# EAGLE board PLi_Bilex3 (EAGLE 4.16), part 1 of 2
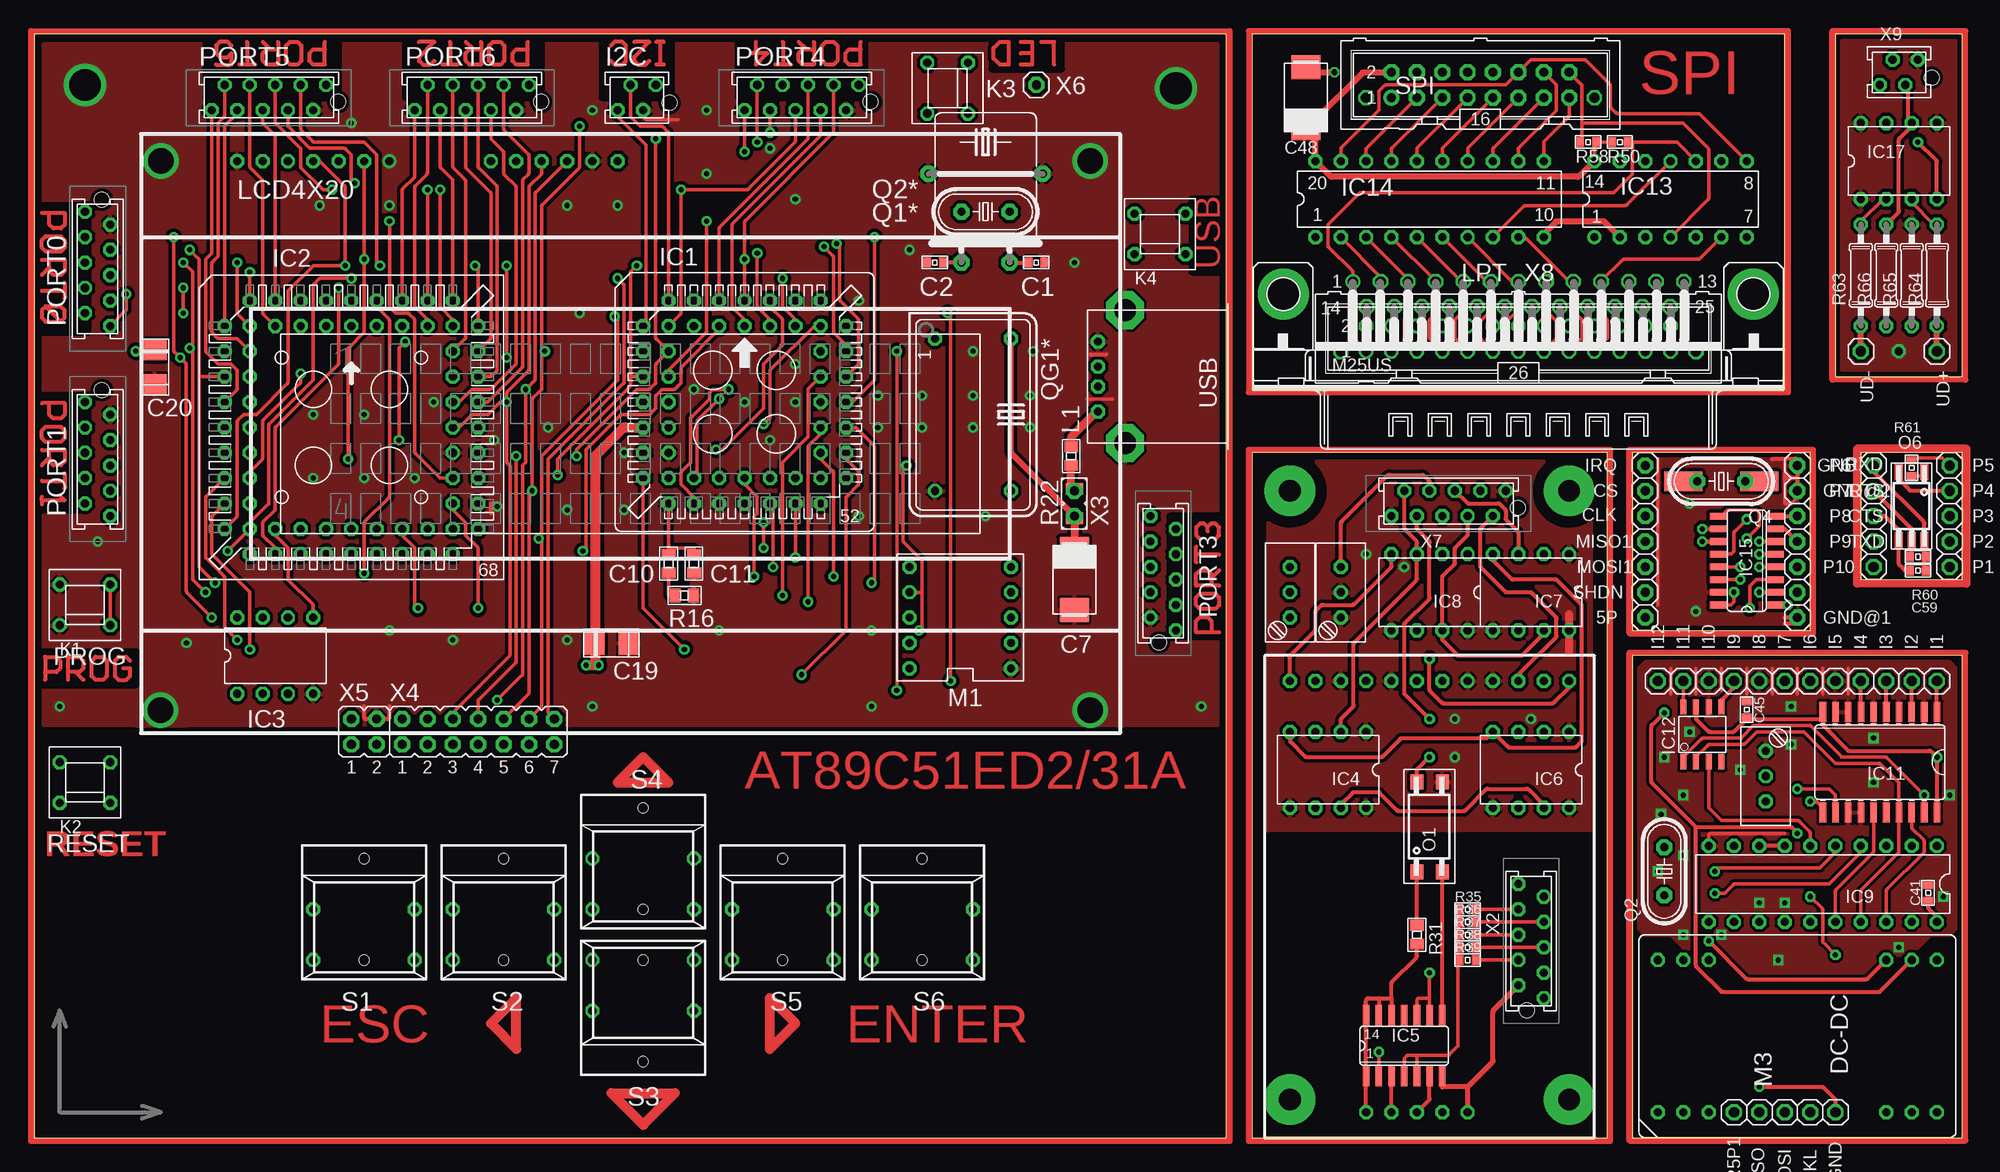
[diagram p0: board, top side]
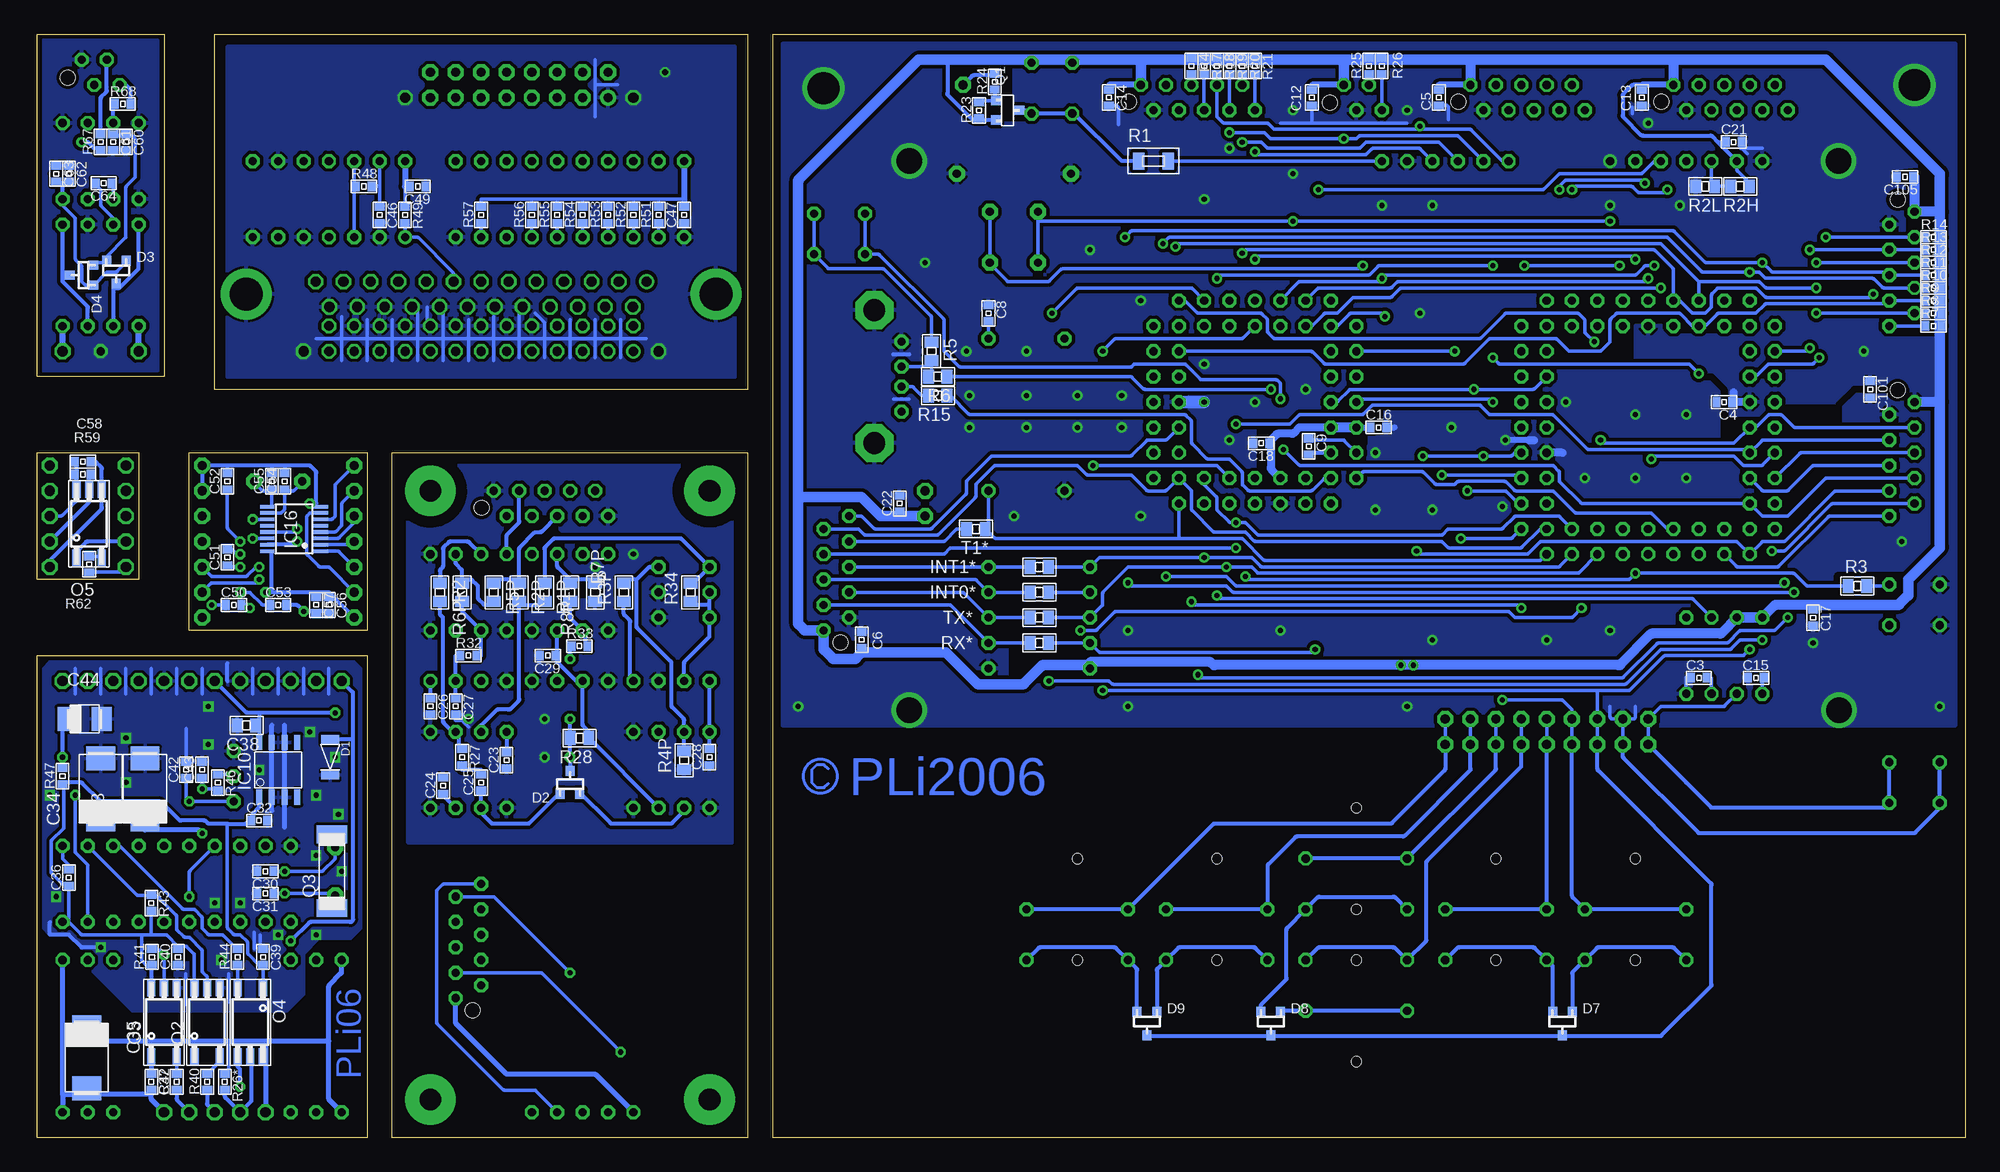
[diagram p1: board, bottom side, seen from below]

Size 193.04 x 110.49 mm. Coordinates in mm from the lower left corner, seen from the top.
Outline: 160.02,50.8 160.02,50.84 160.02,50.8
Outline: 160.02,50.8 177.8,50.8
Outline: 177.8,50.84 177.8,50.8
Outline: 177.8,50.8 177.8,68.58 160.02,68.58
Outline: 160.02,68.54 160.02,68.58
Outline: 160.02,68.58 160.02,50.8
Outline: 193.03,68.58 193.04,68.58
Outline: 193.03,68.58 182.88,68.58 182.88,55.88
Outline: 182.9,55.88 182.88,55.88
Outline: 182.88,55.88 193.03,55.88
Outline: 193.04,55.88 193.03,55.88
Outline: 193.03,55.88 193.03,68.58
Outline: 0,0 119.38,0 119.38,110.49 0,110.49 0,0
Outline: 157.48,68.58 121.92,68.58 121.92,0 157.48,0 157.48,68.58
Outline: 193.03,0.01 193.04,0 193.04,48.26 160.02,48.26 160.02,0 160.03,0.01 193.03,0.01
Outline: 121.92,74.93 175.26,74.93 175.26,110.49 121.92,110.49 121.92,74.93
Outline: 193.04,76.2 193.04,110.49 180.34,110.49 180.34,76.2 193.04,76.2
Copper layers (1*16): Top 0.035mm / dielectric 1.5mm / Bottom 0.035mm
Design rules "default": minimum track width 10mil, minimum drill 24mil, track to track 8mil, track to pad 8mil, pad to pad 8mil, via to via 8mil, smd to smd 8mil, copper to edge 0mil, drill to drill 8mil, minimum pad ring 10mil, minimum via ring 8mil, stop-mask expansion 4mil, vias tented up to drill 20mil, thermal gap 10mil
tRestrict: area 1,62.9 to 5.4,74.3; area 1,80.6 to 5.4,93.3; area 113.7,50.2 to 119.4,62.2; area 0.8,45.3 to 10.2,48.6; area 70.5,104.1 to 83.2,109.9; area 17.1,104.1 to 30.5,109.9; area 56.8,104.1 to 63.8,110.5; area 95.9,107 to 102.9,110.2; area 37.1,104.1 to 50.8,110.5; area 115.9,86.7 to 119.4,94; 30 lines
bRestrict: area 62.2,67.6 to 67,69.5; 87 lines

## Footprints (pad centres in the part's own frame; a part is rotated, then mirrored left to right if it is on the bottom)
MA01-1S = drill 0.914 pad 1.6 octagon: 1 0,0
0603 = smd 0.762 x 0.965: 1 -0.787,0; 2 0.787,0
7243 = smd 2.388 x 2.896: 1 -3.048,0; 2 3.048,0
0805 = smd 1.092 x 1.397: 1 -0.94,0; 2 0.94,0
3528 = smd 2.007 x 2.388: 1 -1.702,0; 2 1.702,0
MA01-1 = drill 1.016 pad 1.6 octagon: 1 0,0
MINIMELF = smd 0.914 x 1.778: A -1.778,0; K 1.778,0
SOT23O = smd 0.9 x 1: 1 -0.989,1.162; 2 0.975,1.147; 3 0,-1.178
MA01-1@2 = drill 1.016 pad 1.6 octagon: 1 0,0
FL04 = drill 0.813 pad 1.397 octagon: 1 0,0; 2 1.27,2.54; 3 2.54,0; 4 3.81,2.54 | hole 1.5: -1.4,1.8
PLCC52 = drill 0.813 pad 1.397 round: 1 0,10.16 | drill 0.813 pad 1.397 octagon: 2 0,7.62; 3 -2.54,10.16; 4 -2.54,7.62; 5 -5.08,10.16; 6 -5.08,7.62; 7 -7.62,10.16; 8 -10.16,7.62; 9 -7.62,7.62; 10 -10.16,5.08; 11 -7.62,5.08; 12 -10.16,2.54; 13 -7.62,2.54; 14 -10.16,0; 15 -7.62,0; 16 -10.16,-2.54; 17 -7.62,-2.54; 18 -10.16,-5.08; 19 -7.62,-5.08; 20 -10.16,-7.62; 21 -7.62,-10.16; 22 -7.62,-7.62; 23 -5.08,-10.16; 24 -5.08,-7.62; 25 -2.54,-10.16; 26 -2.54,-7.62; 27 0,-10.16; 28 0,-7.62; 29 2.54,-10.16; 30 2.54,-7.62; 31 5.08,-10.16; 32 5.08,-7.62; 33 7.62,-10.16; 34 10.16,-7.62; 35 7.62,-7.62; 36 10.16,-5.08; 37 7.62,-5.08; 38 10.16,-2.54; 39 7.62,-2.54; 40 10.16,0; 41 7.62,0; 42 10.16,2.54; 43 7.62,2.54; 44 7.62,5.08; 45 10.16,5.08; 46 10.16,7.62; 47 7.62,10.16; 48 7.62,7.62; 49 5.08,10.16; 50 5.08,7.62; 51 2.54,10.16; 52 2.54,7.62
PLCC-S68 = drill 0.813 pad 1.397 octagon: 1 0,12.7; 2 0,10.16; 3 -2.54,12.7; 4 -2.54,10.16; 5 -5.08,12.7; 6 -5.08,10.16; 7 -7.62,12.7; 8 -7.62,10.16; 9 -10.16,12.7; 10 -12.7,10.16; 11 -10.16,10.16; 12 -12.7,7.62; 13 -10.16,7.62; 14 -12.7,5.08; 15 -10.16,5.08; 16 -12.7,2.54; 17 -10.16,2.54; 18 -12.7,0; 19 -10.16,0; 20 -12.7,-2.54; 21 -10.16,-2.54; 22 -12.7,-5.08; 23 -10.16,-5.08; 24 -12.7,-7.62; 25 -10.16,-7.62; 26 -12.7,-10.16; 27 -10.16,-12.7; 28 -10.16,-10.16; 29 -7.62,-12.7; 30 -7.62,-10.16; 31 -5.08,-12.7; 32 -5.08,-10.16; 33 -2.54,-12.7; 34 -2.54,-10.16; 35 0,-12.7; 36 0,-10.16; 37 2.54,-12.7; 38 2.54,-10.16; 39 5.08,-12.7; 40 5.08,-10.16; 41 7.62,-12.7; 42 7.62,-10.16; 43 10.16,-12.7; 44 12.7,-10.16; 45 10.16,-10.16; 46 12.7,-7.62; 47 10.16,-7.62; 48 12.7,-5.08; 49 10.16,-5.08; 50 12.7,-2.54; 51 10.16,-2.54; 52 12.7,0; 53 10.16,0; 54 12.7,2.54; 55 10.16,2.54; 56 12.7,5.08; 57 10.16,5.08; 58 12.7,7.62; 59 10.16,7.62; 60 12.7,10.16; 61 10.16,12.7; 62 10.16,10.16; 63 7.62,12.7; 64 7.62,10.16; 65 5.08,12.7; 66 5.08,10.16; 67 2.54,12.7; 68 2.54,10.16
DIL08 = drill 0.813 pad 1.397 octagon: 1 0,0; 2 2.54,0; 3 5.08,0; 4 7.62,0; 5 7.62,7.62; 6 5.08,7.62; 7 2.54,7.62; 8 0,7.62
DIL08S = drill 0.813 pad 1.397 octagon: 1 -3.81,-3.81; 2 -1.27,-3.81; 3 1.27,-3.81; 4 3.81,-3.81; 5 3.81,3.81; 6 1.27,3.81; 7 -1.27,3.81; 8 -3.81,3.81
SO14 = smd 0.66 x 2.032: 1 -3.81,-3.073; 2 -2.54,-3.073; 3 -1.27,-3.073; 4 0,-3.073; 5 1.27,-3.073; 6 2.54,-3.073; 7 3.81,-3.073; 8 3.81,3.073; 9 2.54,3.073; 10 1.27,3.073; 11 0,3.073; 12 -1.27,3.073; 13 -2.54,3.073; 14 -3.81,3.073
DIL-20 = drill 0.813 pad 1.397 octagon: 1 -11.43,-3.81; 2 -8.89,-3.81; 3 -6.35,-3.81; 4 -3.81,-3.81; 5 -1.27,-3.81; 6 1.27,-3.81; 7 3.81,-3.81; 8 6.35,-3.81; 9 8.89,-3.81; 10 11.43,-3.81; 11 11.43,3.81; 12 8.89,3.81; 13 6.35,3.81; 14 3.81,3.81; 15 1.27,3.81; 16 -1.27,3.81; 17 -3.81,3.81; 18 -6.35,3.81; 19 -8.89,3.81; 20 -11.43,3.81
SO08 = smd 0.61 x 1.524: 1 -2.54,-2.743; 2 -1.27,-2.743; 3 0,-2.743; 4 1.27,-2.743; 5 1.27,2.743; 6 0,2.743; 7 -1.27,2.743; 8 -2.54,2.743
SO20L = smd 0.66 x 2.032: 1 -5.08,-5.029; 2 -3.81,-5.029; 3 -2.54,-5.029; 4 -1.27,-5.029; 5 0,-5.029; 6 1.27,-5.029; 7 2.54,-5.029; 8 3.81,-5.029; 9 5.08,-5.029; 10 6.35,-5.029; 11 6.35,5.029; 12 5.08,5.029; 13 3.81,5.029; 14 2.54,5.029; 15 1.27,5.029; 16 0,5.029; 17 -1.27,5.029; 18 -2.54,5.029; 19 -3.81,5.029; 20 -5.08,5.029
SO8 = smd 0.61 x 1.524: 1 0,-1.473; 2 1.27,-1.473; 3 2.54,-1.473; 4 3.81,-1.473; 5 3.81,4.013; 6 2.54,4.013; 7 1.27,4.013; 8 0,4.013
DIL14S = drill 0.813 pad 1.397 round: 1 -7.62,-3.81 | drill 0.813 pad 1.397 octagon: 2 -5.08,-3.81; 3 -2.54,-3.81; 4 0,-3.81; 5 2.54,-3.81; 6 5.08,-3.81; 7 7.62,-3.81; 8 7.62,3.81; 9 5.08,3.81; 10 2.54,3.81; 11 0,3.81; 12 -2.54,3.81; 13 -5.08,3.81; 14 -7.62,3.81
DIL20S = drill 0.813 pad 1.397 octagon: 1 -11.43,-3.81; 2 -8.89,-3.81; 3 -6.35,-3.81; 4 -3.81,-3.81; 5 -1.27,-3.81; 6 1.27,-3.81; 7 3.81,-3.81; 8 6.35,-3.81; 9 8.89,-3.81; 10 11.43,-3.81; 11 11.43,3.81; 12 8.89,3.81; 13 6.35,3.81; 14 3.81,3.81; 15 1.27,3.81; 16 -1.27,3.81; 17 -3.81,3.81; 18 -6.35,3.81; 19 -8.89,3.81; 20 -11.43,3.81
SO16S = smd 0.66 x 1.651: 1 -4.445,-2.87; 2 -3.175,-2.87; 3 -1.905,-2.87; 4 -0.635,-2.87; 5 0.635,-2.87; 6 1.905,-2.87; 7 3.175,-2.87; 8 4.445,-2.87; 9 4.445,2.87; 10 3.175,2.87; 11 1.905,2.87; 12 0.635,2.87; 13 -0.635,2.87; 14 -1.905,2.87; 15 -3.175,2.87; 16 -4.445,2.87
QSOP16 = smd 0.356 x 1.422: 1 -2.54,-2.69; 2 -1.905,-2.69; 3 -1.27,-2.69; 4 -0.635,-2.69; 5 0,-2.69; 6 0.635,-2.69; 7 1.27,-2.69; 8 1.905,-2.69; 9 1.905,2.69; 10 1.27,2.69; 11 0.635,2.69; 12 0,2.69; 13 -0.635,2.69; 14 -1.27,2.69; 15 -1.905,2.69; 16 -2.54,2.69
TSS4P = drill 0.813 pad 1.397 octagon: 1 -2.54,-2.032; 2 2.54,-2.032; 3 -2.54,2.032; 4 2.54,2.032
LCD4X20S = drill 0.813 pad 1.397 octagon: 1 0,0; 2 2.54,0; 3 5.08,0; 4 7.62,0; 5 10.16,0; 6 12.7,0; 11 25.4,0; 12 27.94,0; 13 30.48,0; 14 33.02,0; 15 35.56,0; 16 38.1,0 | drill 2.54 pad 2.794 round: GND@1 -7.62,0; GND@2 85.4,0; GND@3 -7.7,-55; GND@4 85.4,-55
ML26S = drill 0.914 pad 1.397 round: 1 -15.24,-1.27 | drill 0.914 pad 1.397 octagon: 2 -15.24,1.27; 3 -12.7,-1.27; 4 -12.7,1.27; 5 -10.16,-1.27; 6 -10.16,1.27; 7 -7.62,-1.27; 8 -7.62,1.27; 9 -5.08,-1.27; 10 -5.08,1.27; 11 -2.54,-1.27; 12 -2.54,1.27; 13 0,-1.27; 14 0,1.27; 15 2.54,-1.27; 16 2.54,1.27; 17 5.08,-1.27; 18 5.08,1.27; 19 7.62,-1.27; 20 7.62,1.27; 21 10.16,-1.27; 22 10.16,1.27; 23 12.7,-1.27; 24 12.7,1.27; 25 15.24,-1.27; 26 15.24,1.27
SUB10 = drill 0.813 pad 1.397 octagon: 1 -5.08,-5.08; 2 -2.54,-5.08; 3 0,-5.08; 4 2.54,-5.08; 5 5.08,-5.08; 6 5.08,5.08; 7 2.54,5.08; 8 0,5.08; 9 -2.54,5.08; 10 -5.08,5.08
OPTOADDA = drill 0.813 pad 1.397 octagon: 1 45.72,2.54; 2 45.72,5.08; 3 45.72,7.62; 4 45.72,10.16; 5 45.72,12.7; 6 45.72,15.24; 7 45.72,17.78; 8 45.72,20.32; 9 45.72,22.86; 10 45.72,25.4; 11 45.72,27.94; 12 45.72,30.48; 16 2.54,22.86; 17 2.54,20.32; 18 2.54,17.78; 19 2.54,15.24; 20 2.54,12.7
UME = drill 0.813 pad 1.397 octagon: 1 -7.62,13.97; 2 -7.62,11.43; 3 -7.62,8.89; 10 -7.62,-8.89; 11 -7.62,-11.43; 12 -7.62,-13.97; 13 7.62,-13.97; 14 7.62,-11.43; 15 7.62,-8.89; 22 7.62,8.89; 23 7.62,11.43; 24 7.62,13.97
LTV816 = smd 1.5 x 1.3: 1 -4.48,1.27; 2 -4.48,-1.27; 3 4.51,-1.27; 4 4.51,1.27
TLP_5P = smd 1.676 x 0.813: 1 -0.254,0; 3 -0.254,-2.54; 4 6.604,-2.54; 5 6.604,-1.27; 6 6.604,0
FL10 = drill 0.813 pad 1.397 octagon: 1 0,0; 2 1.27,2.54; 3 2.54,0; 4 3.81,2.54; 5 5.08,0; 6 6.35,2.54; 7 7.62,0; 8 8.89,2.54; 9 10.16,0; 10 11.43,2.54 | hole 1.5: -1.2,1.7
SOT23O' = smd 0.914 x 1.016: 1 -0.965,1.168; 2 0.965,1.168; 3 0,-1.168
HC49U-LM = drill 0.813 pad 1.6 octagon: 1 -2.413,-5.08; 2 2.413,-5.08; M -5.715,3.81; M1 5.715,3.81
HC49/S = drill 0.813 pad 1.6 octagon: 1 -2.413,0; 2 2.413,0
HC49U-V = drill 0.813 pad 1.6 octagon: 1 -2.413,0; 2 2.413,0
DNT40 = smd 1.778 x 3.048: 1 -3.683,0; 2 3.683,0
HC49SMD = drill 0.813 pad 1.6 octagon: 1@1 -2.413,0; 2@1 2.413,0 | smd 3.81 x 1.93: 1@2 -3.81,0; 2@2 3.81,0
DIL14S' = drill 0.813 pad 1.397 octagon: 1 -7.62,-3.81; 7 7.62,-3.81; 8 7.62,3.81; 14 -7.62,3.81
1206@2 = smd 1.143 x 1.702: 1 -1.473,0; 2 1.473,0
1206 = smd 1.143 x 1.702: 1 -1.473,0; 2 1.473,0
TP_64W = drill 0.813 pad 1.397 octagon: 1 -2.54,0; 2 0,0; 3 2.54,0
0207/10S = drill 0.813 pad 1.397 octagon: 1 -5.08,0; 2 5.08,0
ITT-REK = drill 0.813 pad 1.397 octagon: 1 -5.08,5.08; 2 5.08,5.08; 3 -5.08,0; 4 5.08,0 | hole 1.016: 0,5.08; 0,-5.08
ML16 = drill 0.914 pad 1.6 round: 1 -8.89,-1.27 | drill 0.914 pad 1.6 octagon: 2 -8.89,1.27; 3 -6.35,-1.27; 4 -6.35,1.27; 5 -3.81,-1.27; 6 -3.81,1.27; 7 -1.27,-1.27; 8 -1.27,1.27; 9 1.27,-1.27; 10 1.27,1.27; 11 3.81,-1.27; 12 3.81,1.27; 13 6.35,-1.27; 14 6.35,1.27; 15 8.89,-1.27; 16 8.89,1.27
USBA1 = drill 0.813 pad 1.397 octagon: 1 -3.5,2.71; 2 -1,2.71; 3 1,2.71; 4 3.5,2.71 | drill 2.184 pad 3.81 octagon: 5 -6.65,0; 6 6.65,0
JP1 = drill 0.914 pad 1.6 octagon: 1 0,-1.27; 2 0,1.27
JP7Q = drill 0.914 pad 1.6 octagon: 1 -7.62,-1.27; 2 -7.62,1.27; 3 -5.08,-1.27; 4 -5.08,1.27; 5 -2.54,-1.27; 6 -2.54,1.27; 7 0,-1.27; 8 0,1.27; 9 2.54,-1.27; 10 2.54,1.27; 11 5.08,-1.27; 12 5.08,1.27; 13 7.62,-1.27; 14 7.62,1.27
JP2Q = drill 0.914 pad 1.6 octagon: 1 -1.27,-1.27; 2 -1.27,1.27; 3 1.27,-1.27; 4 1.27,1.27
M25HP = drill 1.016 pad 1.422 round: 1 -16.561,1.27 | drill 1.016 pad 1.422 octagon: 2 -13.792,1.27; 3 -11.049,1.27; 4 -8.28,1.27; 5 -5.512,1.27; 6 -2.769,1.27; 7 0,1.27; 8 2.769,1.27; 9 5.512,1.27; 10 8.28,1.27; 11 11.049,1.27; 12 13.792,1.27; 13 16.561,1.27; 14 -15.189,-1.27; 15 -12.421,-1.27; 16 -9.652,-1.27; 17 -6.909,-1.27; 18 -4.14,-1.27; 19 -1.372,-1.27; 20 1.372,-1.27; 21 4.14,-1.27; 22 6.909,-1.27; 23 9.652,-1.27; 24 12.421,-1.27; 25 15.189,-1.27 | drill 3.302 pad 5.08 round: G1 -23.52,0; G2 23.52,0

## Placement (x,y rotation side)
5P  MA01-1  [MA01-1S]  161.29,52.07 180 top
C1  C_0603  [0603]  100.33,87.63 0 top
C2  C_0603  [0603]  90.17,87.63 180 top
C3  C_0805  [0603]  26.67,46.04 0 bottom
C4  C_0805  [0603]  24.13,73.66 180 bottom
C5  C_0603  [0603]  52.7,104.14 90 bottom
C6  C_0603  [0603]  110.49,49.85 90 bottom
C7  TAJ_D  [7243]  104.14,55.88 270 top
C8  C_0603  [0603]  97.79,82.55 270 bottom
C9  C_0805  [0603]  65.72,69.22 270 bottom
C10  C_0805  [0805]  63.5,57.47 90 top
C11  C_0805  [0805]  66.04,57.47 90 top
C12  C_0603  [0603]  65.41,104.14 270 bottom
C13  C_0603  [0603]  32.38,104.14 270 bottom
C14  C_0603  [0603]  85.72,104.14 270 bottom
C15  C_0603  [0603]  20.95,46.04 180 bottom
C16  C_0603  [0603]  58.74,71.12 0 bottom
C17  C_0603  [0603]  15.24,52.07 270 bottom
C18  C_0603  [0603]  70.48,69.53 180 bottom
C19  TAJ_B  [3528]  57.78,49.53 0 top
C20  TAJ_B  [3528]  12.06,77.15 270 top
C21  C_0603  [0603]  23.18,99.69 0 bottom
C22  C_0603  [0603]  106.68,63.5 90 bottom
C23  C_0805  [0603]  146.05,37.78 90 bottom
C24  C_1206  [0603]  152.4,35.24 90 bottom
C25  C_0805  [0603]  148.59,35.56 90 bottom
C26  C_0603  [0603]  153.67,43.18 270 bottom
C27  C_0603  [0603]  151.13,43.18 270 bottom
C28  C_0603  [0603]  125.73,38.1 90 bottom
C29  C_0603  [0603]  141.92,48.26 180 bottom
C30  C_0805  [0603]  170.18,26.67 180 bottom
C31  C_0805  [0603]  170.18,24.45 180 bottom
C32  100nF  [0603]  170.81,31.75 0 bottom
C33  22µF  [7243]  182.25,34.92 90 bottom
C34  22µF  [7243]  186.69,34.92 90 bottom
C35  22µF  [7243]  188.09,8 270 bottom
C36  1µF  [0603]  189.87,26.04 90 bottom
C37  100nF  [0603]  181.61,5.59 270 bottom
C38  220nF  [0805]  172.09,41.27 180 bottom
C39  100nF  [0603]  170.42,18.1 270 bottom
C40  100nF  [0603]  178.94,18.1 90 bottom
C41  100n  [0603]  189.61,24.51 90 top
C42  TAJ_A  [0603]  178.12,36.83 90 bottom
C43  10nF  [0603]  176.53,36.83 90 bottom
C44  TAJ_A  [3528]  188.28,41.91 0 bottom
C45  C_0603  [0603]  171.45,42.86 270 top
C46  470pF  [0603]  158.75,92.39 270 bottom
C47  100nF  [0603]  128.27,92.39 90 bottom
C48  22µF  [7243]  127.32,104.14 90 top
C49  100nF  [0603]  154.94,95.25 180 bottom
C50  100nF  [0603]  173.35,53.34 0 bottom
C51  100nF  [0603]  173.99,58.1 90 bottom
C52  100nF  [0603]  173.99,65.72 90 bottom
C53  100nF  [0603]  168.91,53.34 0 bottom
C54  22pF  [0603]  168.28,65.72 90 bottom
C55  22pF  [0603]  169.54,65.72 90 bottom
C56  100nF  [0603]  163.83,53.34 270 bottom
C57  1µF  [0603]  165.1,53.34 270 bottom
C58  C_0603  [0603]  188.47,67.69 0 bottom
C59  C_0603  [0603]  188.59,56.77 180 top
C60  1µ  [0603]  184.15,99.69 270 bottom
C61  100n  [0603]  185.42,99.69 270 bottom
C62  1µ  [0603]  189.87,96.52 270 bottom
C63  100n  [0603]  191.13,96.52 270 bottom
C64  C_0805  [0603]  186.37,95.57 180 bottom
C101  C_0603  [0603]  9.53,74.93 270 bottom
C105  C_0603  [0603]  6.03,96.2 180 bottom
CKL  MA01-1  [MA01-1]  177.8,2.54 270 top
CLK  MA01-1  [MA01-1S]  161.29,62.23 180 top
CS  MA01-1  [MA01-1S]  161.29,64.77 180 top
CTS  MA01-1  [MA01-1S]  176.53,57.15 0 top
D1  BZW03XX  [MINIMELF]  163.7,38.1 270 bottom
D2  BAT54A  [SOT23O]  139.7,35.56 180 bottom
D3  BAT54S  [SOT23O]  185.1,86.68 0 bottom
D4  BAT54S  [SOT23O]  188.59,86.36 270 bottom
D7  BAT54C  [SOT23O]  40.32,11.43 0 bottom
D8  BAT54C  [SOT23O]  69.53,11.43 0 bottom
D9  BAT54C  [SOT23O]  81.92,11.43 0 bottom
GND  MA01-1  [MA01-1S]  176.53,67.31 0 top
GND@1  MA01-1  [MA01-1S]  176.53,52.07 0 top
GND@2  MA01-1  [MA01-1S]  176.53,64.77 0 top
I1  MA01-1  [MA01-1@2]  190.5,45.72 90 top
I2  MA01-1  [MA01-1@2]  187.96,45.72 90 top
I2C  FL04S  [FL04]  62.23,105.41 180 top
I3  MA01-1  [MA01-1@2]  185.42,45.72 90 top
I4  MA01-1  [MA01-1@2]  182.88,45.72 90 top
I5  MA01-1  [MA01-1@2]  180.34,45.72 90 top
I6  MA01-1  [MA01-1@2]  177.8,45.72 90 top
I7  MA01-1  [MA01-1@2]  175.26,45.72 90 top
I8  MA01-1  [MA01-1@2]  172.72,45.72 90 top
I9  MA01-1  [MA01-1@2]  170.18,45.72 90 top
I10  MA01-1  [MA01-1@2]  167.64,45.72 90 top
I11  MA01-1  [MA01-1@2]  165.1,45.72 90 top
I12  MA01-1  [MA01-1@2]  162.56,45.72 90 top
IC1  AT80C5131A-UM  [PLCC52]  71.12,73.66 0 top
IC2  AT89C51ED2  [PLCC-S68]  31.75,71.12 0 top
IC3  TL7705P  [DIL08]  20.32,44.45 0 top
IC4  LTC1049S  [DIL08S]  129.54,36.83 180 top
IC5  7408  [SO14]  137.16,9.21 0 top
IC6  LTC1049S  [DIL08S]  149.86,36.83 180 top
IC7  LTC1049S  [DIL08S]  149.86,54.61 180 top
IC8  LTC1049S  [DIL08S]  139.7,54.61 180 top
IC9  89C2051P  [DIL-20]  179.07,25.4 180 top
IC10  78L05S  [SO08]  168.28,36.83 0 bottom
IC11  MAX186S  [SO20L]  185.42,37.59 180 top
IC12  LTC1446S  [SO8]  165.1,39.12 0 top
IC13  74HC86  [DIL14S]  163.83,93.98 0 top
IC14  74HC541  [DIL20S]  139.7,93.98 0 top
IC15  MAX202CPE  [SO16S]  171.45,57.78 90 top
IC16  MAX3100S  [QSOP16]  167.32,61.28 90 bottom
IC17  LTC1049P  [DIL08S]  186.69,97.79 0 top
INT0*  0  [0805]  92.71,54.61 180 bottom
INT1*  0  [0805]  92.71,57.15 180 bottom
IRQ  MA01-1  [MA01-1S]  161.29,67.31 180 top
K1  TSS4P  [TSS4P]  5.08,53.34 0 top
K2  TSS4P  [TSS4P]  5.08,35.56 0 top
K3  TSS4P  [TSS4P]  91.44,105.09 90 top
K4  TSS4P  [TSS4P]  112.71,90.49 0 top
L1  0805  [0805]  103.82,68.26 270 top
LCD4X20  LCD4X20S  [LCD4X20S]  20.32,97.79 0 top
LPT  ML26  [ML26S]  148.59,80.01 0 top
M1  SUB_RS232  [SUB10]  92.71,52.07 90 top
M2  OPTOADDA  [OPTOADDA]  156.21,0 90 top
M3  UM30BR12  [UME]  176.53,10.16 90 top
MISO  MA01-1  [MA01-1]  172.72,2.54 270 top
MISO1  MA01-1  [MA01-1S]  161.29,59.69 180 top
MOSI  MA01-1  [MA01-1]  175.26,2.54 270 top
MOSI1  MA01-1  [MA01-1S]  161.29,57.15 180 top
O1  LTV816  [LTV816]  139.7,31.11 90 top
O2  TLP113S  [TLP_5P]  177.29,8.38 90 bottom
O3  TLP113S  [TLP_5P]  181.61,8.38 90 bottom
O4  TLP113S  [TLP_5P]  170.43,14.73 270 bottom
O5  TLP113S  [TLP_5P]  189.1,58.29 90 bottom
O6  TLP113S  [TLP_5P]  189.23,66.42 270 top
P1  MA01-1  [MA01-1@2]  191.77,57.15 0 top
P2  MA01-1  [MA01-1@2]  191.77,59.69 0 top
P3  MA01-1  [MA01-1@2]  191.77,62.23 0 top
P4  MA01-1  [MA01-1@2]  191.77,64.77 0 top
P5  MA01-1  [MA01-1@2]  191.77,67.31 0 top
P6  MA01-1  [MA01-1@2]  184.15,67.31 180 top
P7  MA01-1  [MA01-1@2]  184.15,64.77 180 top
P8  MA01-1  [MA01-1@2]  184.15,62.23 180 top
P9  MA01-1  [MA01-1@2]  184.15,59.69 180 top
P10  MA01-1  [MA01-1@2]  184.15,57.15 180 top
PORT0  FL10S  [FL10]  5.08,92.71 270 top
PORT1  FL10S  [FL10]  5.08,73.66 270 top
PORT3  FL10  [FL10]  114.3,50.8 90 top
PORT4  FL10S  [FL10]  82.55,105.41 180 top
PORT5  FL10S  [FL10]  29.21,105.41 180 top
PORT6  FL10S  [FL10]  49.53,105.41 180 top
Q1  BC307  [SOT23O']  95.89,102.87 90 bottom
Q1*  HC49U-LM  [HC49U-LM]  95.25,92.71 0 top
Q2  SM49  [HC49/S]  163.19,26.67 90 top
Q2*  HC49U-V  [HC49U-V]  95.25,92.71 180 top
Q3  HC49U-V  [DNT40]  163.51,26.67 90 bottom
Q4  HC49SMD  [HC49SMD]  168.91,65.72 180 top
QG1*  XO-14  [DIL14S']  93.98,72.39 270 top
R1  27  [1206@2]  81.28,97.79 0 bottom
R1P  10K  [0805]  142.24,54.61 270 bottom
R2  10K  [0805]  152.72,54.61 270 bottom
R2H  0805  [0805]  22.54,95.25 180 bottom
R2L  1K5  [0805]  26.04,95.25 180 bottom
R2P  100K  [0805]  144.78,54.61 270 bottom
R3  0805  [0805]  10.79,55.24 0 bottom
R3P  18K  [0805]  134.3,54.61 90 bottom
R4  0805  [0603]  77.47,107.31 270 bottom
R4P  2K  [0805]  128.27,37.78 90 bottom
R5  0805  [0805]  103.5,78.74 270 bottom
R5P  100K  [0805]  147.32,54.61 270 bottom
R5P1  MA01-1  [MA01-1@2]  170.18,2.54 270 top
R6  0805  [0805]  102.87,76.2 180 bottom
R6P  10K  [0805]  150.5,54.61 90 bottom
R7  0805  [0603]  3.17,81.28 0 bottom
R7P  2K  [0805]  137.16,54.61 90 bottom
R8  0805  [0603]  3.17,82.55 0 bottom
R8P  18K  [0805]  139.7,54.61 270 bottom
R9  0805  [0603]  3.17,83.82 0 bottom
R10  0805  [0603]  3.17,85.09 0 bottom
R11  0805  [0603]  3.17,86.36 0 bottom
R12  0805  [0603]  3.17,87.63 0 bottom
R13  0805  [0603]  3.17,88.9 0 bottom
R14  0805  [0603]  3.17,90.17 0 bottom
R15  0805  [0805]  102.87,74.3 180 bottom
R16  0805  [0805]  65.09,54.29 180 top
R17  0805  [0603]  76.2,107.31 270 bottom
R18  0805  [0603]  74.93,107.31 270 bottom
R19  0805  [0603]  73.66,107.31 270 bottom
R20  0805  [0603]  72.39,107.31 270 bottom
R21  0805  [0603]  71.12,107.31 270 bottom
R22  1206  [1206]  104.14,63.5 90 top
R23  0805  [0603]  98.74,102.87 90 bottom
R24  0805  [0603]  97.16,105.73 90 bottom
R25  0805  [0603]  59.69,107.31 90 bottom
R26  0805  [0603]  58.42,107.31 90 bottom
R26*  2K2  [0603]  174.24,5.59 270 bottom
R27  0207/10  [0603]  150.5,38.1 270 bottom
R28  5K1  [0805]  138.75,40.01 180 bottom
R29  TP_64W  [TP_64W]  130.81,54.61 90 top
R30  TP_64W  [TP_64W]  125.73,54.61 90 top
R31  0805  [0805]  138.43,20.32 270 top
R32  0805  [0603]  149.86,48.26 0 bottom
R33  0805  [0603]  138.75,49.21 0 bottom
R34  0805  [0805]  127.64,54.61 90 bottom
R35  0805  [0603]  143.51,22.86 0 top
R36  0805  [0603]  143.51,21.59 0 top
R37  0805  [0603]  143.51,20.32 0 top
R38  0805  [0603]  143.51,19.05 0 top
R39  0805  [0603]  143.51,17.78 0 top
R40  2K2  [0603]  176.02,5.59 90 bottom
R41  2K2  [0603]  181.55,18.1 90 bottom
R42  2K2  [0603]  179.07,5.59 90 bottom
R43  2K2  [0603]  181.61,23.5 270 bottom
R44  2K2  [0603]  172.97,18.1 90 bottom
R45  TP_64W  [TP_64W]  173.35,36.2 270 top
R46  0805  [0603]  174.94,35.56 270 bottom
R47  0805  [0603]  190.5,36.2 90 bottom
R48  1K  [0603]  160.34,95.25 0 bottom
R49  0805  [0603]  156.21,92.39 270 bottom
R50  0805  [0603]  158.75,99.69 180 top
R51  0805  [0603]  130.81,92.39 90 bottom
R52  0805  [0603]  133.35,92.39 90 bottom
R53  0805  [0603]  135.89,92.39 90 bottom
R54  0805  [0603]  138.43,92.39 90 bottom
R55  0805  [0603]  140.97,92.39 90 bottom
R56  0805  [0603]  143.51,92.39 90 bottom
R57  0805  [0603]  148.59,92.39 90 bottom
R58  0805  [0603]  155.57,99.69 0 top
R59  0805  [0603]  188.47,66.42 180 bottom
R60  0805  [0603]  188.59,58.17 0 top
R61  0805  [0603]  187.96,67.06 90 top
R62  0805  [0603]  187.83,57.4 90 bottom
R63  1M  [0207/10S]  182.88,86.36 90 top
R64  1M  [0207/10S]  190.5,86.36 90 top
R65  100K  [0207/10S]  187.96,86.36 90 top
R66  100K  [0207/10S]  185.42,86.36 90 top
R67  0805  [0603]  186.69,99.69 90 bottom
R68  0805  [0603]  184.47,103.5 0 bottom
RGND  MA01-1  [MA01-1@2]  180.34,2.54 270 top
RTS  MA01-1  [MA01-1S]  176.53,59.69 0 top
RX*  0  [0805]  92.71,49.53 180 bottom
RXD  MA01-1  [MA01-1S]  176.53,62.23 0 top
S1  ITT-REK  [ITT-REK]  33.02,22.86 180 top
S2  ITT-REK  [ITT-REK]  46.99,22.86 180 top
S3  ITT-REK  [ITT-REK]  60.96,12.7 0 top
S4  ITT-REK  [ITT-REK]  60.96,27.94 180 top
S5  ITT-REK  [ITT-REK]  74.93,22.86 180 top
S6  ITT-REK  [ITT-REK]  88.9,22.86 180 top
SHDN  MA01-1  [MA01-1S]  161.29,54.61 180 top
SPI  ML16  [ML16]  144.78,105.41 0 top
T1*  0805  [0805]  99.06,60.96 180 bottom
TX*  0  [0805]  92.71,52.07 180 bottom
TXD  MA01-1  [MA01-1S]  176.53,54.61 0 top
U$1  [PROG]  0.95,45.72 0 top
U$3  [COPY]  114.62,36.2 0 bottom
U$4  [P5]  29.21,109.86 180 top
U$5  [P4]  82.87,109.86 180 top
U$6  [PI2C]  63.18,109.86 180 top
U$7  [P1]  0.64,73.66 270 top
U$9  [P2]  49.53,109.86 180 top
U$11  [P3]  118.75,50.48 90 top
U$12  [P0]  0.64,92.71 270 top
U$18  [T_LED]  102.23,109.86 180 top
UD+  MA01-1  [MA01-1@2]  190.5,78.74 270 top
UD-  MA01-1  [MA01-1@2]  182.88,78.74 270 top
X1  USBB  [USBA1]  109.22,76.2 90 top
X2  FL10S  [FL10]  151.13,13.97 90 top
X3  JP1QS  [JP1]  104.14,63.5 180 top
X4  JP7QS  [JP7Q]  44.45,40.64 0 top
X5  JP2QS  [JP2Q]  33.02,40.64 0 top
X6  MA01-1  [MA01-1S]  100.33,105.41 0 top
X7  FL10S  [FL10]  147.32,64.77 180 top
X8  M25HPS  [M25HP]  148.59,84.45 0 top
X9  FL04  [FL04]  188.59,107.95 180 top

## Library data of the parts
5P CLK CS CTS GND GND@1 GND@2 IRQ MISO1 MOSI1 RTS RXD SHDN TXD X6 = CON-LSTB
C1-C18 C21-C43 C45-C64 C101 C105 R27 R59 = SMD_C
C19 C20 = SMD
C44 = SMD_C@2
CKL I1-I12 MISO MOSI P1-P10 R5P1 RGND UD+ UD- = CON-LSTB@2
D1 O2-O6 = DNT1@2
D2-D4 D7-D9 = SMD_D
I2C PORT0 PORT1 PORT3-PORT6 X9 = CON-ML
IC1 LCD4X20 U$1 U$3-U$7 U$9 U$11 U$12 U$18 = MICRO
IC2 = ATMEL
IC3 M1 = NETZTEIL
IC4 IC6-IC8 IC17 = DIL
IC5 = 74XXSMD
IC9 = ATMEL@2
IC10 = V-REG
IC11 IC12 = NETZTEIL@3
IC13 IC14 = 74XX
IC15 = LIB_PLI
IC16 = MAXIM
INT0* INT1* L1 R1 R1P R2 R2H R2L R2P R3 R3P R4 R4P R5 R5P R6 R6P R7 R7P R8 R8P R9-R26 R26* R28 R31-R34 R40-R44 R46-R58 R67 R68 RX* T1* TX* = R
K1-K4 S1-S6 = KEY
LPT SPI = CON-ML@3
M2 = NETZTEIL@2
M3 = DC-DC
O1 = DNT1
Q1 = NPN
Q1* Q2* QG1* = QUARTZ
Q2 Q3 = QUARTZ@2
Q4 = QUARTZ@3
R29 R30 R35-R39 R45 R60-R62 = R@2
R63-R66 = R@3
X1 = CON-USB
X2 X7 = CON-ML@2
X3-X5 = JUMPS
X8 = SUBD-US

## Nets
1NI: C23.2 C28.2 IC4.4 IC6.4 IC7.4 IC8.4 M2.12 X7.3
5P: C4.1 C5.2 C6.1 C7.1 C8.2 C12.1 C13.1 C14.1 C16.1 C17.1 C18.1 C19.1 C20.1 C21.1 C22.1 C101.1 C105.1 I2C.1 IC1.16 IC1.17 IC1.26 IC2.2 IC2.17 IC3.7 IC3.8 K3.2 K3.4 LCD4X20.2 M1.10 PORT0.1 PORT1.1 PORT3.1 PORT4.1 PORT5.1 PORT6.1 Q1.1 QG1*.14 R2H.1 R4.1 R7.2 R8.2 R9.2 R10.2 R11.2 R12.2 R13.2 R14.2 R17.1 R18.1 R19.1 R20.1 R21.1 R22.1 R23.1 R25.2 R26.2 X3.2
5P1: IC5.1 IC5.12 IC5.13 IC5.14 M2.16 R31.2 X2.1
5P2: C32.1 C34.1 C36.1 C39.2 C40.2 C41.1 IC9.20 IC10.1 O2.6 O3.6 O4.1 R41.1 R43.2 R47.1
5P3: C47.2 C48.1 C49.2 IC13.14 IC14.20 R49.1 R50.2 R51.2 R52.2 R53.2 R54.2 R55.2 R56.2 R57.2 R58.2 SPI.2
5PH: C44.1 C45.2 IC11.10 IC11.20 IC12.7 R47.2
12HN: D1.A I12.1 M3.15
12HP: C33.1 C38.1 I7.1 IC10.8 M3.14
12PI: C24.1 C29.1 IC4.7 IC6.7 IC7.7 IC8.7 M2.7 R28.1 X7.4
+LED: LCD4X20.16 R1.2
AGND: C23.1 C24.2 C26.2 C27.2 C28.1 C29.2 IC4.1 IC4.5 IC4.8 IC6.1 IC6.5 IC6.8 IC7.1 IC7.5 IC7.8 IC8.5 IC8.8 M2.4 M2.5 M2.8 M2.10 O1.3 R4P.1 R7P.1 R29.1 R29.2 X7.1 X7.10
CLK: IC9.19 IC11.19 IC12.1
CS_D: IC9.6 IC12.3
DI: IC9.17 IC11.17 IC12.2
DO: IC9.16 IC11.15
GND: C1.2 C2.2 C3.1 C4.2 C5.1 C6.2 C7.2 C8.1 C9.2 C11.1 C12.2 C13.2 C14.2 C15.2 C16.2 C17.2 C18.2 C19.2 C20.2 C21.2 C22.2 C101.2 C105.2 I2C.2 IC1.19 IC1.25 IC1.41 IC2.51 IC3.4 K1.1 K1.3 K2.1 K2.3 LCD4X20.1 LCD4X20.15 LCD4X20.GND@1 LCD4X20.GND@2 LCD4X20.GND@3 LCD4X20.GND@4 M1.1 PORT0.2 PORT1.2 PORT3.2 PORT4.2 PORT5.2 PORT6.2 Q1*.M Q1*.M1 QG1*.7 R2L.2 R16.1 X1.4 X1.5 X1.6 X5.3 X5.4
GND1: IC5.7 M2.20 X2.2
GND2: C30.2 C31.2 C32.2 C33.2 C34.2 C38.2 C39.1 C40.1 C41.2 C42.2 C43.2 C44.2 C45.1 D1.K I5.1 I8.1 I10.1 IC9.10 IC10.2 IC10.3 IC10.6 IC10.7 IC11.2 IC11.4 IC11.6 IC11.8 IC11.9 IC11.13 IC11.14 IC12.6 O2.4 O3.4 R45.1
GND3: C46.2 C47.1 C48.2 C49.1 IC13.2 IC13.5 IC13.7 IC13.9 IC14.1 IC14.10 LPT.10 LPT.12 LPT.14 LPT.16 LPT.18 LPT.20 LPT.22 LPT.24 SPI.1 X8.18 X8.19 X8.20 X8.21 X8.22 X8.23 X8.24 X8.25 X8.G1 X8.G2
GND4: C52.2 C53.2 C54.2 C55.2 C56.2 C57.2 GND.1 GND@1.1 GND@2.1 IC15.15 IC16.8
GND5: C60.2 C61.2 C62.1 C63.1 IC17.1 IC17.5 IC17.8 R65.2 X9.1
I_IST: IC8.6 R8P.2 R33.2
MISO: MISO.1 O4.5 R26*.2
MOSI: CKL.1 R42.1
N$2: K1.2 K1.4 R3.2
N$3: L1.1 X1.1
N$5: LCD4X20.3 R2H.2 R2L.1
N$8: R5.2 R6.2 X1.3
N$9: Q1.2 R23.2 R24.1
N$10: D7.2 S1.1 S1.2
N$11: D7.1 S2.1 S2.2
N$12: R15.2 X1.2
N$13: PORT3.8 T1*.2
N$14: D8.2 S3.3 S3.4
N$15: D9.2 S5.1 S5.2
N$16: D9.1 S6.1 S6.2
N$17: I2C.4 IC1.8 R26.1
N$18: L1.2 R22.2 X3.1
N$19: D8.1 S4.1 S4.2
N$20: I2C.3 IC1.7 R25.1
N$21: K3.1 K3.3 Q1.3 R1.1
N$23: IC1.24 K4.1 K4.3
N$24: R24.2 X6.1
N$25: C15.1 IC3.1
N$26: C10.1 R16.2
N$27: C3.2 IC3.3
N$28: D2.3 O1.4 R28.2 X7.8
N$29: IC8.2 R7P.2 R8P.1
N$30: IC6.2 R2.2 R27.1
N$31: C25.1 D2.2 IC6.6
N$32: IC7.2 R5P.2 R6P.2
N$33: IC7.6 R6P.1 R32.2
N$34: IC4.2 IC8.3 X7.9
N$35: IC4.3 R3P.2 R4P.2 R29.3 X7.7
N$36: C25.2 R27.2
N$37: IC6.3 R1P.2 R2P.2
N$38: R1P.1 R30.3 R34.2
N$39: M2.11 R30.1 R30.2 R34.1
N$40: M2.9 R3P.1
N$41: D2.1 IC4.6
N$42: O1.1 R31.1
N$43: IC5.8 O1.2
N$44: C27.1 M2.2 R32.1
N$45: C26.1 M2.1 R33.1
N$46: IC5.3 M2.17
N$47: IC5.6 M2.18
N$48: IC5.4 IC5.5 R35.1 R36.1 R37.1 R38.1 R39.1
N$49: IC5.9 IC5.10 X2.9
N$50: M2.3 X7.2
N$56: IC5.2 X2.3
N$57: M2.19 X2.10
N$58: R35.2 X2.8
N$59: R36.2 X2.7
N$60: R37.2 X2.6
N$61: R38.2 X2.5
N$62: R39.2 X2.4
N$63: IC9.18 IC11.18
N$64: C30.1 IC9.5 Q2.2 Q3.2
N$65: C31.1 IC9.4 Q2.1 Q3.1
N$66: O2.3 R40.2
N$67: IC9.7 IC9.8 O3.5 R41.2
N$68: O3.3 R42.2
N$69: C36.2 IC9.1
N$70: IC9.11
N$71: O4.3 R44.1
N$72: I1.1 IC11.1
N$73: I2.1 IC11.3
N$74: I3.1 IC11.5
N$75: I4.1 IC11.7
N$76: I9.1 IC12.5
N$77: I11.1 IC12.8
N$78: R45.2 R46.1
N$80: IC13.10 LPT.1 R50.1 X8.1
N$81: IC14.2 LPT.3 R51.1 X8.2
N$82: IC14.3 LPT.5 R52.1 X8.3
N$83: IC14.4 LPT.7 R53.1 X8.4
N$84: IC14.5 LPT.9 R54.1 X8.5
N$85: IC14.6 LPT.11 R55.1 X8.6
N$86: IC13.6 LPT.19 X8.10
N$87: IC13.8 IC14.19 SPI.12
N$88: IC13.3 IC13.12 R48.1
N$89: IC14.9 LPT.17 R57.1 X8.9
N$90: C46.1 IC13.13 R48.2
N$91: IC14.7 LPT.13 R56.1 X8.7
N$92: IC13.1 LPT.15 R49.2 X8.8
N$93: IC13.11 IC14.8
N$94: IC14.18 SPI.3
N$95: IC14.17 SPI.5
N$96: IC14.16 SPI.7
N$97: IC14.15 SPI.9
N$98: IC14.14 SPI.11
N$99: IC14.13 SPI.13
N$100: IC14.11 SPI.15
N$101: IC13.4 R58.1 SPI.16
N$102: IC14.12 SPI.14
N$104: IC15.7 RTS.1
N$105: IC15.14 TXD.1
N$106: IC15.8 RXD.1
N$107: C51.1 IC15.4
N$108: C51.2 IC15.5
N$109: C50.2 IC15.3
N$111: IC16.1 MOSI1.1
N$112: IC16.2 MISO1.1
N$113: CLK.1 IC16.3
N$114: CS.1 IC16.4
N$115: C55.1 IC16.9 Q4.1@1
N$116: C54.1 IC16.10 Q4.2@1
N$117: IC15.12 IC16.11
N$118: IC15.10 IC16.13
N$119: IC15.11 IC16.15
N$120: IC15.9 IC16.14
N$121: IC16.6 IRQ.1
N$122: IC16.7 SHDN.1
N$123: C50.1 IC15.1
N$124: D4.3 IC17.3 R64.2 R65.1
N$126: C64.2 IC17.6 R66.2 X9.2
N$127: R64.1 UD+.1
N$128: R63.1 UD-.1
N$131: C64.1 D3.3 IC17.2 R63.2 R66.1
N$132: O6.3 P4.1
N$133: C59.2 O6.4 P8.1
N$134: P5.1 R61.2
N$135: O6.5 P7.1 R60.1
N$136: C58.2 O5.4 P1.1
N$137: O5.5 P2.1 R59.1
N$138: C58.1 O5.6 P3.1 R59.2
N$139: C59.1 O6.6 P6.1 R60.2
N$140: O5.1 P9.1
N$142: O6.1 R61.1
N$143: P10.1 R62.1
N$144: O5.3 R62.2
N$145: R67.2 X9.3
N$146: R68.2 X9.4
N$147: C62.2 C63.2 D3.2 D4.2 IC17.4 R67.1
N$149: C60.1 C61.1 D3.1 D4.1 IC17.7 R68.1
P00: IC1.36 IC2.15 PORT0.3 R14.1
P01: IC1.37 IC2.14 PORT0.4 R13.1
P02: IC1.38 IC2.12 PORT0.5 R12.1
P03: IC1.40 IC2.11 PORT0.6 R11.1
P3A0: M1.2 PORT3.3 RX*.2
P3A1: M1.3 PORT3.4 TX*.2
P3A2: INT0*.2 M1.4 PORT3.5
P3A3: INT1*.2 M1.5 PORT3.6
P04: IC1.42 IC2.9 PORT0.7 R10.1
P05: IC1.44 IC2.6 PORT0.8 R9.1
P06: IC1.45 IC2.5 PORT0.9 R8.1
P07: IC1.52 IC2.3 PORT0.10 R7.1
P10: IC1.47 IC2.19 PORT1.3
P11: IC1.48 IC2.21 PORT1.4
P12: IC1.49 IC2.22 PORT1.5
P13: IC1.50 IC2.23 PORT1.6
P14: IC1.51 IC2.25 PORT1.7
P15: IC1.4 IC2.27 PORT1.8
P16: IC1.5 IC2.28 PORT1.9
P17: IC1.6 IC2.29 PORT1.10
P30: IC1.20 IC2.34 M1.9 RX*.1
P31: IC1.29 IC2.39 M1.8 TX*.1
P32: IC1.30 IC2.40 INT0*.1 M1.7
P33: IC1.31 IC2.41 INT1*.1 M1.6
P34: IC1.32 IC2.42 PORT3.7
P35: IC1.33 IC2.43 QG1*.8 T1*.1
P36: IC1.35 IC2.45 PORT3.9
P37: IC1.39 IC2.47 PORT3.10
P40: IC1.1 IC2.20 LCD4X20.6 PORT4.3
P41: D7.3 D8.3 D9.3 IC1.2 IC2.24 PORT4.4 X4.1 X4.2
P42: IC1.3 IC2.26 LCD4X20.4 PORT4.5 R4.2 S6.3 S6.4 X4.13 X4.14
P43: IC1.9 IC2.44 LCD4X20.5 PORT4.6 R17.2 S5.3 S5.4 X4.11 X4.12
P44: IC1.10 IC2.46 LCD4X20.11 PORT4.7 R18.2 S4.3 S4.4 X4.9 X4.10
P45: IC1.11 IC2.50 LCD4X20.12 PORT4.8 R19.2 S3.1 S3.2 X4.7 X4.8
P46: IC1.14 IC2.53 LCD4X20.13 PORT4.9 R20.2 S2.3 S2.4 X4.5 X4.6
P47: IC1.15 IC2.57 LCD4X20.14 PORT4.10 R21.2 S1.3 S1.4 X4.3 X4.4
P50: IC2.60 PORT5.3
P51: IC2.62 PORT5.4
P52: IC2.63 PORT5.5
P53: IC2.7 PORT5.6
P54: IC2.8 PORT5.7
P55: IC2.10 PORT5.8
P56: IC2.13 PORT5.9
P57: IC2.16 PORT5.10
P60: IC2.54 PORT6.3
P61: IC2.55 PORT6.4
P62: IC2.56 PORT6.5
P63: IC2.58 PORT6.6
P64: IC2.59 PORT6.7
P65: IC2.61 PORT6.8
P66: IC2.64 PORT6.9
P67: IC2.65 PORT6.10
PGND: IC7.3 R2.1 X7.5
PLFF: C10.2 C11.2 IC1.21
PSEN: IC1.28 IC2.67 R3.1
R1IN: CTS.1 IC15.13
R5P: C35.1 C37.1 M3.1 M3.24 O2.1 O3.1 O4.6 R5P1.1 R26*.1
RGND: C35.2 C37.2 M3.12 M3.13 O4.4 RGND.1
RIN: IC3.2 K2.2 K2.4 X5.1 X5.2
RSTN: IC2.30 IC3.5
RSTP: IC1.43 IC3.6
RX: IC9.2 O2.5 R43.1
SCK: MOSI.1 R40.1
TX: IC9.3 R44.2
UA-: R2P.1 R5P.1 X7.6
UCAP: C9.1 IC1.18
USB0: K4.2 K4.4 R5.1
USB1: IC1.23 R6.1
USB2: IC1.22 R15.1
V+: C53.1 IC15.2
V-: C52.1 IC15.6
VADJ: C43.1 IC11.12 R46.2
VCC: 5P.1 C56.1 C57.1 IC15.16 IC16.16
VREF: C42.1 IC11.11 R45.3
XTAL1: C2.1 IC1.13 IC2.49 Q1*.1 Q2*.2
XTAL2: C1.1 IC1.12 IC2.48 Q1*.2 Q2*.1

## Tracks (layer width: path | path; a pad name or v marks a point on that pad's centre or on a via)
1NI
  Top 0.406: IC4.4 125.73,39.79 arc45 125.8,39.61 127.24,38.17 arc45 127.42,38.1 134.83,38.1 arc45 135.01,38.17 136.77,39.93 arc-45 136.95,40.01 145.41,40.01 IC6.4 147.56,39.13 arc45 147.74,39.05 154.2,39.05 arc45 154.38,39.13 154.87,39.61 arc45 154.94,39.79 154.94,53.23 arc45 154.87,53.41 152.47,55.81 arc45 152.29,55.88 148.06,55.88 arc-45 147.88,55.95 146.12,57.71 arc-45 146.05,57.89 IC7.4 | M2.12 125.73,48.16 arc-45 125.8,48.33 128.2,50.73 arc45 128.27,50.91 128.27,52.6 arc-45 128.34,52.78 128.83,53.27 arc-45 129.01,53.34 131.97,53.34 arc45 132.15,53.41 135.82,57.08 arc45 135.89,57.26 IC8.4
  Bottom 0.406: M2.12 IC4.4 C28.2 | IC6.4 C23.2 | IC7.4 146.05,60.22 arc45 145.98,60.4 144.85,61.52 arc-45 144.78,61.7 X7.3
5P  (via drill 0.51 pad 1.02)
  Top 0.61: X3.2 97.86,68.51 arc-45 97.79,68.69 QG1*.14
  Top 0.813: X3.2 R22.1 C7.1 | 56.2,49.53 C19.1 | v10.16,78.74 12.06,78.74 C20.1
  Top 1.016: IC1.16 59.16,71.12 arc45 58.98,71.05 56.27,68.34 arc45 56.2,68.16 56.2,49.53 56.2,47.31 | 56.2,47.31 v56.52,47.31 | v55.24,47.31 56.2,47.31
  Bottom 0.356: 71.12,107.95 R21.1 | 72.39,107.95 R20.1 | 73.66,107.95 R19.1 | 74.93,107.95 R18.1 | 76.2,107.95 R17.1 | 77.47,107.95 R4.1 | Q1.1 96.84,101.91 96.84,101.92 | 98.74,101.92 R23.1 | 58.42,107.95 R26.2 | 59.69,107.95 R25.2 | QG1*.14 C8.2 | R2H.1 21.59,95.57 22.79,96.76 arc45 22.86,96.94 LCD4X20.2 | 15.24,53.34 C17.1 | 24.77,99.69 C21.1 | 106.68,62.23 C22.1
  Bottom 0.406: 52.7,105.41 C5.2 | 85.72,105.41 C14.1 | 2.54,90.17 R14.2 | 2.54,88.9 R13.2 | 2.54,87.63 R12.2 | 2.54,86.36 R11.2 | 2.54,81.28 R7.2 | 2.54,82.55 R8.2 | 2.54,83.82 R9.2 | 2.54,85.09 R10.2 | 65.41,105.41 C12.1 | 110.49,48.58 C6.1 | 5.08,96.2 C105.1 | C13.1 32.38,105.41 33.23,105.41 arc-45 33.41,105.34 34.22,104.53 arc-45 34.29,104.35 34.29,102.34 arc-45 34.22,102.16 32.46,100.4 arc-45 32.28,100.33 25.5,100.33 arc45 25.33,100.26 24.77,99.69 LCD4X20.2 | 101.92,107.95 101.92,104.56 arc-45 101.84,104.38 99.45,101.99 arc-45 99.27,101.92 98.74,101.92 96.84,101.92 | 69.53,69.53 C18.1
  Bottom 0.61: IC1.16 C16.1 | PORT6.1 52.7,105.41 | PORT5.1 32.38,105.41 | I2C.1 65.41,105.41 | PORT4.1 85.72,105.41
  Bottom 0.813: IC1.26 69.46,66.92 arc45 69.53,67.1 69.53,69.53 69.53,69.85 68.97,70.41 arc45 68.79,70.48 67.42,70.48 arc-45 67.24,70.56 66.75,71.05 arc45 66.57,71.12 IC1.17 | IC2.17 23.18,73.66 | 23.18,73.66 C4.1 | 23.18,73.66 23.18,74.61
  Bottom 1.016: IC1.16 IC1.17 | 87.63,47.31 87.63,47.62 75.67,47.62 arc45 75.49,47.55 75.32,47.38 arc-45 75.14,47.31 v56.52,47.31 v55.24,47.31 34.71,47.31 | 15.24,53.34 18.95,53.34 arc-45 19.12,53.27 IC3.8 | IC3.7 24.37,50.56 arc45 24.55,50.48 31.33,50.48 arc-45 31.51,50.41 34.53,47.38 | 2.54,92.71 PORT0.1 5.08,96.2 | 29.21,107.95 PORT5.1 | 49.53,107.95 PORT6.1 | 2.54,73.66 PORT1.1 | 93.47,107.95 K3.2 | 89.41,107.95 K3.4
  Bottom 1.067: 62.23,107.95 59.69,107.95 58.42,107.95 49.53,107.95 29.21,107.95 14.07,107.95 arc45 13.9,107.88 2.61,96.59 arc45 2.54,96.42 2.54,92.71 2.54,90.17 2.54,88.9 2.54,87.63 2.54,86.36 2.54,85.09 2.54,83.82 2.54,82.55 2.54,81.28 2.54,73.66 2.54,59.16 arc45 2.61,58.98 5.64,55.95 arc-45 5.71,55.77 5.71,54.4 arc45 5.79,54.22 6.59,53.41 arc45 6.77,53.34 15.24,53.34 | M1.10 87.63,47.31 92.29,47.31 arc-45 92.47,47.23 94.22,45.48 arc45 94.4,45.4 98.76,45.4 arc45 98.94,45.48 101.97,48.5 arc-45 102.15,48.58 110.49,48.58 111.05,48.02 arc45 111.23,47.94 113.24,47.94 arc45 113.42,48.02 114.23,48.82 arc45 114.3,49 PORT3.1 116.1,50.8 arc45 116.28,50.87 116.77,51.36 arc45 116.84,51.54 116.84,64.14 | 62.23,107.95 71.12,107.95 72.39,107.95 73.66,107.95 74.93,107.95 76.2,107.95 77.47,107.95 82.55,107.95 | 116.84,64.14 116.84,95.78 arc45 116.77,95.96 104.85,107.88 arc45 104.67,107.95 101.92,107.95 93.47,107.95 89.41,107.95 82.55,107.95 | 34.53,47.38 arc45 34.71,47.31 | IC3.8 IC3.7 | 62.23,107.95 I2C.1 | 82.55,107.95 PORT4.1 | X3.2 106.68,62.23 108.48,62.23 arc45 108.66,62.3 110.42,64.06 arc-45 110.59,64.14 116.84,64.14
  pour Bottom (isolate 0.356): 2.54,80.01 8.26,80.01 8.26,82.55 21.59,82.55 22.23,80.33 29.21,80.33 29.21,81.28 33.02,81.28 33.02,77.79 27.62,77.79 23.81,73.98 23.81,72.39 19.05,72.39 17.78,73.66 12.38,73.66 10.79,75.25 5.4,75.25 5.4,73.66 2.54,73.66
5P1
  Top 0.406: 134.62,13.97 133.6,13.97 arc90 133.35,13.72 IC5.14 IC5.1 M2.16 | 134.62,13.97 135.89,13.97 | 135.89,13.97 135.89,15.45 arc-45 135.96,15.63 138.36,18.02 arc45 138.43,18.2 R31.2 | 135.89,13.97 IC5.12 | 134.62,13.97 IC5.13
  Bottom 0.508: M2.16 137.09,6.28 arc-45 137.26,6.35 145.94,6.35 arc45 146.12,6.42 151.06,11.36 arc45 151.13,11.54 X2.1
5P2
  Top 0.406: IC9.20 190.5,22.1 189.69,22.91 arc-45 189.61,23.09 C41.1
  Bottom 0.356: 189.87,25.4 189.87,21.59 | 189.87,21.59 IC9.20 | 189.87,21.59 188.67,20.39 arc-45 188.49,20.32 182.56,20.32 | 182.56,20.32 181.61,20.32 | 178.94,19.18 178.22,19.18 arc45 178.04,19.1 177.37,18.43 arc45 177.29,18.25 O2.6 | 182.56,20.32 182.56,17.82 arc-45 182.49,17.64 182.06,17.22 arc-45 181.89,17.14 181.61,17.14 | 181.61,20.32 R43.2 | 181.61,20.32 180.19,20.32 arc45 180.01,20.25 178.94,19.18 | 178.94,19.18 C40.2 | 189.87,25.4 C36.1 | 190.37,35.56 190.37,31.09 arc45 190.45,30.91 191.57,29.79 arc-45 191.64,29.61 191.64,26.65 arc-45 191.57,26.47 190.57,25.47 arc-45 190.4,25.4 189.87,25.4 | 173.99,31.43 173.99,21.06 arc-45 173.92,20.88 173.43,20.39 arc-45 173.25,20.32 172.82,20.32 arc45 172.65,20.25 172.03,19.63 arc45 171.96,19.45 171.96,18.52 arc-45 171.88,18.34 170.85,17.31 C39.2 170.42,15.25 170.43,15.24 O4.1
  Bottom 0.406: 186.69,33.66 180.76,33.66 arc45 180.58,33.58 178.83,31.82 arc-45 178.65,31.75 176.32,31.75 arc45 176.14,31.68 175.97,31.51 arc-45 175.79,31.43 173.99,31.43 172.19,31.43 arc-45 172.01,31.51 171.77,31.75 C32.1 171.45,31.75 171.45,32.34 arc45 171.38,32.52 170.89,33.01 arc-45 170.81,33.19 IC10.1 | 186.69,33.66 188.52,35.49 arc-45 188.7,35.56 190.37,35.56 190.5,35.56 R47.1 | 186.69,33.66 C34.1 | O3.6 181.61,17.14 181.55,17.21 R41.1
5P3
  Top 0.356: 156.21,99.69 R58.2 156.53,99.69 | 156.53,99.69 R50.2 | 156.21,99.69 IC13.14 | 156.21,99.69 156.53,99.69
  Top 0.61: IC13.14 154.7,96.28 arc-45 154.52,96.2 129.96,96.2 arc-45 129.78,96.28 IC14.20 128.27,101.09 | SPI.2 133.14,106.68 arc45 132.96,106.61 128.27,101.92 128.27,101.09 | 128.27,101.09 C48.1
  Bottom 0.356: R57.2 148.59,93.98 143.51,93.98 | 143.51,93.98 R56.2 | 140.97,93.98 143.51,93.98 | 140.97,93.98 R55.2 | 138.43,93.98 140.97,93.98 | 138.43,93.98 R54.2 | 135.89,93.98 138.43,93.98 | 135.89,93.98 R53.2 | 133.35,93.98 135.89,93.98 | 133.35,93.98 R52.2 | 130.81,93.98 R51.2 | 130.81,93.98 133.35,93.98 | 128.27,93.98 130.81,93.98 | 156.21,95.25 R49.1
  Bottom 0.61: C47.2 128.27,93.98 IC14.20 | IC13.14 156.21,95.25 C49.2
5PH  (via drill 0.51 pad 1.02)
  Top 0.356: 179.07,41.91 179.07,43.18
  Top 0.406: 171.45,41.91 179.07,41.91 | 171.45,41.91 170.25,40.71 arc-45 170.07,40.64 167.75,40.64 arc-45 167.57,40.71 166.44,41.84 arc-45 166.37,42.02 IC12.7 | IC11.20 v190.5,38.1 189.94,38.66 arc45 189.76,38.73 181.72,38.73 arc-45 181.54,38.81 179.14,41.2 arc-45 179.07,41.38 179.07,41.91 | 179.07,41.91 IC11.10 | 171.45,41.91 C45.2
  Bottom 0.356: 190.5,41.91 C44.1
  Bottom 0.406: R47.2 v190.5,38.1 190.5,41.91
12HN  (via drill 0.51 pad 1.02)
  Top 0.406: v167.64,19.68 171.38,15.95 arc45 171.56,15.88 183.41,15.88 arc45 183.59,15.95 M3.15
  Bottom 0.406: v167.64,19.68 165.81,21.52 arc45 165.63,21.59 161.71,21.59 arc-45 161.53,21.66 161.49,21.71 arc-45 161.42,21.89 161.42,39.88 | 161.42,39.88 D1.A | 161.42,39.88 161.42,44.47 arc-45 161.49,44.65 I12.1
12HP  (via drill 0.51 pad 1.02)
  Top 0.406: v163.19,42.55 162,41.35 arc45 161.93,41.17 161.93,35.66 arc45 162,35.49 166.37,31.11 | 166.37,31.11 175.79,31.11 arc-45 175.97,31.04 v176.53,30.48 | M3.14 184.86,14.68 arc-45 184.68,14.61 169.01,14.61 arc-45 168.84,14.68 166.44,17.07 arc-45 166.37,17.25 166.37,31.11
  Bottom 0.406: 170.81,41.27 IC10.8 | 170.81,41.27 C38.1 | 170.81,42.55 171.98,42.55 arc45 172.16,42.62 I7.1 | v163.19,42.55 170.81,42.55 | 170.81,42.55 170.81,41.27
  Bottom 0.508: v176.53,30.48 176.85,30.8 182.25,30.8 C33.1
12PI
  Top 0.406: X7.4 143.51,60.43 arc-45 143.44,60.25 142.31,59.13 arc45 142.24,58.95 142.24,57.57 arc-45 142.17,57.39 141.04,56.27 arc45 140.97,56.09 IC8.7 140.97,49.95 arc45 141.04,49.77 142.48,48.33 arc45 142.66,48.26 148.8,48.26 arc45 148.98,48.33 151.13,50.48 IC7.7 | IC6.7 151.13,33.34 149.62,34.85 arc45 149.44,34.92 145.52,34.92 arc45 145.34,34.85 143.27,32.78 arc-45 143.09,32.7 136.63,32.7 arc-45 136.45,32.78 134.69,34.53 arc45 134.51,34.61 132.19,34.61 arc45 132.01,34.53 130.88,33.41 arc45 130.81,33.23 IC4.7
  Bottom 0.406: 137.79,40.01 R28.1 | 137.79,40.01 137.79,40.64 138.36,41.2 arc45 138.43,41.38 M2.7 139.06,45.72 140.9,47.55 arc45 140.97,47.73 140.97,48.26 | 140.97,48.26 C29.1 | C24.1 152.4,34.29 IC6.7 | IC4.7 137.79,40.01 | 140.97,48.26 IC8.7
+LED
  Bottom 0.356: LCD4X20.16 R1.2
AGND  (via drill 0.51 pad 1.02)
  Top 0.813: 153.67,48.58 153.67,52.39
  Bottom 0.356: 151.13,42.55 151.13,41.78 150.5,41.78 149.86,41.15
  other vias: 142.24,38.1 142.24,41.91 133.35,58.42 149.86,41.91 137.16,57.15
  pour Bottom (isolate 0.356): 123.51,29.53 155.89,29.53 155.89,67.31 123.51,67.31
  pour Top (isolate 0.356): 123.51,30.8 155.89,30.8 155.89,67.63 123.51,67.63
CLK  (via drill 0.51 pad 1.02)
  Top 0.356: 189.23,31.75 IC11.19 v189.23,34.29 185.49,38.03 arc45 185.31,38.1 181.08,38.1 arc-45 180.9,38.17 177.87,41.2 arc45 177.69,41.27 172.25,41.27 arc45 172.07,41.2 170.95,40.08 arc-45 170.77,40.01 167.11,40.01 arc45 166.93,39.93 165.1,38.1 IC12.1
  Bottom 0.356: IC9.19 187.96,27.2 arc-45 188.03,27.38 189.16,28.5 arc45 189.23,28.68 v189.23,34.29
CS_D
  Top 0.356: IC9.6 177.8,30.5 arc45 177.73,30.68 176.73,31.68 arc45 176.55,31.75 169.01,31.75 arc-45 168.84,31.82 167.71,32.95 arc-45 167.64,33.12 IC12.3
DI
  Top 0.356: IC9.17 182.88,24.66 arc-45 182.95,24.84 186.62,28.5 arc45 186.69,28.68 IC11.17 186.69,35.45 arc45 186.62,35.63 184.86,37.39 arc45 184.68,37.47 180.44,37.47 arc-45 180.27,37.54 177.24,40.57 arc45 177.06,40.64 172.57,40.64 arc45 172.39,40.57 171.27,39.44 arc-45 171.09,39.37 167.75,39.37 arc45 167.57,39.3 166.37,38.1 IC12.2 166.37,37.59
DO
  Top 0.356: IC9.16 180.34,24.66 arc-45 180.41,24.84 184.08,28.5 arc45 184.15,28.68 IC11.15
GND  (via drill 0.51 pad 1.02, 0.81 pad 1.4, 3.2 pad 3.81)
  Top 0.356: 60.96,102.55 60.96,102.23 61.2,101.99 arc45 61.38,101.92 64.45,101.92 | 105.41,73.98 107.95,73.98
  Top 0.406: 105.73,78.42 107.31,78.42 | 33.02,43.18 33.02,42.16 arc90 33.27,41.91 35.31,41.91 arc90 35.56,42.16 35.56,43.18
  Top 0.457: 45.72,62.55 45.72,63.5
  Bottom 0.356: C15.2 21.59,46.04 | X5.3 X5.4 | X5.4 33.27,41.91 arc-90 33.02,42.16 33.02,43.18 | X5.4 35.31,41.91 arc90 35.56,42.16 35.56,43.18 | 105.73,73.98 107.31,73.98 | 33.34,103.19 33.34,102.55 | 84.77,101.41 84.77,103.06 arc-90 85.03,103.31 85.28,103.31 | 52.58,103.38 52.01,103.38 arc90 51.75,103.12 51.75,101.92 | 55.88,101.6 65.41,101.6 | 65.41,101.6 68.58,101.6 | 65.41,101.6 C12.2 65.41,103.5 | 22.35,99.06 20.32,99.06 | 22.35,99.06 22.54,99.06 | 21.84,98.55 22.35,99.06
  Bottom 0.406: 105.73,78.42 107.31,78.42 | X5.3 34.29,38.2 arc-45 34.22,38.03 26.74,30.55 arc-45 26.57,30.48 5.18,30.48 arc-45 5.01,30.55 2.54,33.02 K2.1 K2.3 | C3.1 27.94,46.04 IC3.4 | C9.2 65.72,68.58 IC1.19
  Bottom 0.61: 43.69,69.85 v46.04,69.85 | C16.2 57.15,71.12
  Bottom 0.813: 40.32,68.58 IC2.51 | 43.69,69.85 43.18,69.85
  Bottom 1.27: v76.2,73.66 IC1.41
  other vias: 93.98,74.3 27.94,72.39 51.44,71.12 40.01,73.66 59.05,68.58 41.91,49.85 53.34,49.85 15.24,49.53 84.45,74.3 71.12,73.66 35.56,50.8 53.34,93.34 87.63,88.9 27.94,66.04 54.61,82.55 68.58,50.8 5.08,105.41 114.3,105.09 38.1,66.04 55.88,43.18 84.45,71.12 53.34,62.87 35.56,93.34 46.35,63.18 59.05,62.87 73.66,69.85 93.98,71.12 35.56,97.79 67.31,96.52 82.55,62.23 95.25,62.23 99.69,74.3 83.82,50.8 93.98,78.74 88.9,74.3 88.9,71.12 99.69,71.12 83.82,43.18 58.42,93.34 116.84,43.18 2.54,43.18 66.04,74.93 76.2,77.47 104.14,87.63 100.01,78.74 76.2,93.98 6.35,59.69 82.55,83.82 33.02,66.04 33.02,72.39 73.66,99.06 67.31,102.87 55.88,102.87 28.57,93.34 31.75,101.6
  pour Top (isolate 0.356): 0.95,41.27 0.95,109.54 118.43,109.54 118.43,41.27
  pour Bottom (isolate 0.356): 0.95,109.54 118.43,109.54 118.43,41.27 0.95,41.27
  pour Top (isolate 0.356, no thermals): 10.16,100.01 15.24,100.01 15.24,95.57 10.16,95.57
  pour Top (isolate 0.356, no thermals): 10.16,41.27 15.24,41.27 15.24,45.09 10.16,45.09
  pour Top (isolate 0.356, no thermals): 103.5,41.27 103.5,44.45 103.5,45.09 107.95,45.09 107.95,41.27
  pour Top (isolate 0.356, no thermals): 103.82,99.69 107.63,99.69 107.63,95.89 103.82,95.89
  pour Bottom (isolate 0.356, no thermals): 10.16,100.33 15.24,100.33 15.24,95.25 10.16,95.25
  pour Bottom (isolate 0.356, no thermals): 10.16,41.27 10.16,45.09 15.24,45.09 15.24,41.27
  pour Bottom (isolate 0.356, no thermals): 103.5,41.27 103.5,44.77 107.95,44.77 107.95,41.27
  pour Bottom (isolate 0.356, no thermals): 103.5,95.25 103.5,100.33 107.95,100.33 107.95,95.25
GND1
  Top 0.406: 140.97,5.08 IC5.7
  Top 0.508: 143.51,5.08 140.97,5.08 | 143.51,5.08 145.98,7.55 arc45 146.05,7.72 146.05,12.6 arc-45 146.12,12.77 X2.2 | M2.20 143.51,5.08
GND2  (via drill 0.51 pad 1.02)
  Top 0.356: 168.91,44.77 168.91,46.99 | 166.37,44.45 166.37,46.99 | 171.45,44.45 171.45,46.99 | 173.99,44.45 173.99,46.99 | 181.61,44.45 181.61,46.99 | 179.07,44.45 179.07,46.99 | 163.83,44.45 163.83,46.99 | IC9.10 167.64,30.23 arc-90 167.89,30.48 175.26,30.48 | 176.53,44.45 176.53,46.99
  Top 0.406: IC11.9 180.34,41.91
  Bottom 0.356: 166.37,44.45 166.37,46.99 | 163.83,44.45 163.83,46.99 | 168.91,44.45 168.91,46.99 | 171.45,44.45 171.45,46.99 | 181.61,44.45 181.61,46.99 | 179.07,44.45 179.07,46.99 | 176.53,44.45 176.53,46.99 | 170.69,18.92 170.69,20.32 | 173.86,13.59 173.86,16.38 | 178.18,13.34 178.18,16.38 | 171.32,18.92 171.32,20.57 | C42.2 178.12,40.96 | 184.15,44.45 184.15,46.99 | 186.69,44.45 186.69,46.99 | 189.23,44.45 189.23,46.99
  Bottom 0.406: v186.69,19.05 188.59,19.05 189.87,20.32 191.77,20.32 191.77,21.59 | 173.99,45.72 173.99,47.5
  Bottom 0.508: 168.28,31.11 IC10.3 168.28,41.27 | 169.54,32.77 IC10.2 169.54,41.27
  other vias: 175.9,43.18 170.81,36.83 165.1,34.29 172.72,23.5 184.15,35.56 191.13,24.13 191.77,34.29 165.1,28.26 163.19,38.1 175.9,39.37 184.15,40.01 175.26,23.5 174.62,17.78 165.1,20.32 168.91,20.32 165.74,40.64 162.88,32.38 162.56,26.67
  pour Bottom (isolate 0.305): 191.77,20.32 189.87,20.32 187.96,18.41 187.96,17.14 183.51,12.7 168.02,12.7 166.37,14.35 166.37,18.41 164.85,19.94 161.67,19.94 160.66,20.95 160.66,46.99 161.29,47.62 191.77,47.62 192.41,46.99 192.41,20.95
  pour Top (isolate 0.305): 187.96,13.97 187.96,18.41 189.87,20.32 191.77,20.32 192.41,20.95 192.41,46.99 191.77,47.62 161.29,47.62 160.66,46.99 160.66,20.95 161.29,20.32 163.83,20.32 165.1,19.05 165.1,16.51 168.91,12.7 186.69,12.7
GND3  (via drill 0.61 pad 1.02, 1.02 pad 1.42)
  Top 0.406: C48.2 127.32,106.68
  Top 0.61: 127.32,106.68 v130.18,106.68 | IC14.10 151.13,90.49 152.33,91.68 arc-45 152.5,91.76 157.06,91.76 arc-45 157.24,91.68 IC13.2
  Bottom 0.356: 134.62,80.01 132.08,80.01 | 134.62,80.01 137.16,80.01 | 137.16,80.01 139.7,80.01 | 139.7,80.01 142.24,80.01 | 142.24,80.01 144.78,80.01 | 144.78,80.01 147.32,80.01 | 147.32,80.01 149.86,80.01 | 149.86,80.01 152.4,80.01 | 152.4,80.01 154.94,80.01 | 154.94,80.01 157.48,80.01 | 157.48,80.01 160.02,80.01 | 160.02,80.01 162.56,80.01 | 162.56,80.01 165.1,80.01 | 162.56,80.01 162.56,82.23 | 153.99,81.28 153.99,83.19 | 149.86,80.01 149.86,77.79 | 149.86,80.01 149.86,81.92 | 147.32,80.01 147.32,82.23 | 147.32,80.01 147.32,77.79 | 134.62,80.01 134.62,81.92 | 134.62,78.11 134.62,80.01 | 137.16,80.01 137.16,81.92 | 137.16,80.01 137.16,78.11 | 139.7,80.01 139.7,81.92 | 139.7,80.01 139.7,78.11 | 142.24,80.01 142.24,81.6 143.19,82.55 | 142.24,80.01 142.24,78.11 | 144.78,80.01 144.78,82.55 | 144.78,80.01 144.78,78.11 | 152.4,80.01 152.4,82.55 | 152.4,80.01 152.4,77.79 | 154.94,80.01 154.94,82.87 | 154.94,80.01 154.94,77.79 | 157.48,80.01 157.48,81.92 | 157.48,80.01 157.48,77.79 | 160.02,80.01 160.02,81.92 | 160.02,80.01 160.02,77.79 | 162.56,80.01 162.56,77.79 | 137.16,105.41 137.16,102.23 | 137.16,105.41 137.16,107.95 | 134.94,105.41 137.16,105.41
  other vias: 130.81,78.74 166.37,78.74 156.21,104.14 133.35,104.14
  pour Bottom (isolate 0.356): 123.19,109.22 173.99,109.22 173.99,76.2 123.19,76.2
GND4  (via drill 0.51 pad 1.02)
  Top 0.356: 176.53,64.14 175.9,63.5 175.26,63.5 175.26,66.04 175.26,67.94 | 162.56,53.34 162.56,67.94
  Top 0.406: 175.26,51.44 176.53,51.44 GND@1.1 175.26,52.07 | 173.99,67.94 175.26,67.94 176.53,67.94 GND.1 176.53,66.04 | 176.53,66.04 176.53,64.14 | 176.53,66.04 175.26,66.04
  Bottom 0.356: 165.1,63.18 IC16.8 164.47,63.18 | 165.1,52.7 C57.2
  Bottom 0.406: C56.2 163.83,52.7 165.1,52.7 v166.37,52.7 166.93,53.27 arc-45 167.11,53.34 C53.2 | 169.54,67.31 173.99,67.31 | 173.99,67.31 C52.2 | 169.54,67.31 C55.2 | 165.1,63.18 165.1,63.5 | 173.99,67.31 GND.1 GND@2.1 | 168.28,67.31 169.54,67.31 | 165.1,63.5 v165.74,63.5 | 165.1,63.5 165.1,66.57 arc-45 165.17,66.75 165.66,67.24 arc-45 165.84,67.31 168.28,67.31 | 168.28,67.31 C54.2
  pour Top (isolate 0.356): 162.56,67.94 176.53,67.94 176.53,51.44 162.56,51.44
GND5  (via drill 0.81 pad 1.4)
  other vias: 186.69,78.74
  pour Bottom (isolate 0.356): 180.97,76.83 180.97,109.86 192.41,109.86 192.41,76.83
  pour Top (isolate 0.356): 180.97,76.83 180.97,109.86 192.41,109.86 192.41,76.83
I_IST
  Bottom 0.406: R8P.2 139.7,52.17 arc-45 139.63,52 IC8.6 138.11,50.48 138.11,49.21 R33.2
MISO
  Bottom 0.406: O4.5 171.58,8 171.58,3.79 arc45 171.65,3.61 MISO.1 174.17,3.99 arc45 174.24,4.17 R26*.2
MOSI
  Bottom 0.406: R42.1 179.07,3.92 arc-45 179,3.74 CKL.1
N$1
  Top 1.016: 48.26,8.89 48.26,13.97 45.72,11.43 48.26,8.89
N$2
  Top 0.356: K1.2 K1.4
  Bottom 0.356: K1.4 7.75,55.24 R3.2
N$3
  Top 0.356: 106.36,72.7 X1.1
  Top 0.813: L1.1 103.82,69.22 103.82,70.06 arc-45 103.9,70.24 106.36,72.7
N$4
  Top 1.016: 73.66,8.89 73.66,13.97 76.2,11.43 73.66,8.89
N$5
  Bottom 0.356: 25.4,95.25 LCD4X20.3 | R2H.2 R2L.1
  Bottom 0.406: R2L.1 25.4,95.25
N$6
  Top 1.016: 57.78,4.45 64.14,4.45 60.96,1.27 57.78,4.45
N$7
  Top 1.016: 58.42,35.56 63.5,35.56 60.96,38.1 58.42,35.56
N$8
  Bottom 0.356: R6.2 103.5,76.2 103.5,77.2 | 103.5,77.2 X1.3 | 103.5,77.2 R5.2
N$9
  Bottom 0.356: 97.16,103.82 R24.1 | R23.2 98.74,103.82 97.16,103.82 | Q1.2 96.83,103.83 96.84,103.82 97.16,103.82
N$10
  Bottom 0.406: S1.2 29.14,18.98 arc-45 29.32,19.05 36.73,19.05 arc-45 36.9,18.98 S1.1 39.27,16.61 arc-45 39.35,16.43 D7.2
N$11
  Bottom 0.406: S2.1 50.87,18.98 arc45 50.7,19.05 43.28,19.05 arc45 43.11,18.98 S2.2 41.39,17.26 arc45 41.31,17.08 D7.1
N$12
  Bottom 0.356: R15.2 104.35,74.3 arc45 104.53,74.37 105.29,75.13 arc-45 105.47,75.2 X1.2
N$13
  Bottom 0.356: T1*.2 100.86,60.96 arc-45 101.04,60.89 102.16,59.76 arc45 102.34,59.69 PORT3.8
N$14
  Bottom 0.406: S3.3 S3.4 68.26,12.7 68.39,12.58 D8.2
N$15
